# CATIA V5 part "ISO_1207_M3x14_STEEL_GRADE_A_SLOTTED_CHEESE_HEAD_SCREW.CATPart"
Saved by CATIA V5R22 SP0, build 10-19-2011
Part number: ISO 1207 SCREW M3x14 STEEL GRADE A SLOTTED CHEESE HEAD
Publications: "Mating Face", "Axis"
Bounding box of the stored display mesh (mm): x -16 to 0, y -2.741 to 2.741, z -2.75 to 2.75
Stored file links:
  D:\PER\CAO_PER_MODIF_2025\CAO_PER_pick&place_2024P\Sous_Ensemble_Flacon\ISO_1207_M3x14_STEEL_GRADE_A_SLOTTED_CHEESE_HEAD_SCREW.CATPart
  C:\Program Files\Dassault Systemes\B22\win_b64\startup\components\MechanicalStandardParts\EN_Standards\Design_Tables\EN_ISO_1207_GRADE_A_SLOTTED_CHEESE_HEAD_SCREW.txt
  C:\Program Files\Dassault Systemes\B22\win_b64\startup\components\MechanicalStandardParts\ISO_Standards\Design_Tables\ISO_1207_GRADE_A_SLOTTED_CHEESE_HEAD_SCREW.txt
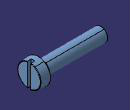
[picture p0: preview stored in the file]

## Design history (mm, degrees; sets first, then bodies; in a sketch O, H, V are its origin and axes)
Parameters
  d_dia = 3 mm
  dk_nom_head_dia = 5.5 mm
  k_max_head_depth = 2 mm
  n_nom_Slot_Width = 0.8 mm
  t_min_Slot_Depth = 0.85 mm
  r_min = 0.1 mm
  p_pitch = 0.5 mm
  Threading = 13 mm
  l_Length_nom = 14 mm
Body1 "PartBody" (main body)
  Sketch1 on zx-plane, origin (0, 0, 0), H (-1, 0, 0), V (0, 0, 1)
    line L1 (0, 0) -> (0, 2.575)
    line L2 (0, 2.575) -> (2, 2.75)
    point P2 (2, 2.75)
    line L3 (2, 2.75) -> (2, 1.4375)
    axis line L4 (-15.2845, 0) -> (155.0819, 0)
    reference intersected line E1 through (1000000, 0) direction (-1, 0) from xy-plane
    line L5 (2, 1.4375) -> (2.5, 1.4375)
    point P5 (3, 1.5)
    line L6 (3, 1.5) -> (16, 1.5)
    point P6 (16, 1.5)
    line L7 (16, 1.5) -> (16, 0)
    point P7 (16, 0)
    line L8 (3, 1.5) -> (2.5, 1.4375)
    point P9 (2.5, 1.4375)
    distance L1 P2 = 2 {= k_max_head_depth}
    distance P2 L4 = 2.75 {= dk_nom_head_dia /2}
    angle L4 L2 = 175
    length L7 = 1.5 {= d_dia /2}
    distance L5 L4 = 1.4375 {= (d_dia -(p_pitch/4))/2}
    distance P6 P5 = 13 {= Threading}
    distance L7 L1 = 16 {= l_Length_nom +k_max_head_depth}
    distance P9 P5 H = 0.5 {= p_pitch}
    vertical: L1 V, L3 V, L7 V
    horizontal: L4 H, L5 H
    coincidence: L4 E1, P7 L4
    parallelism: L6 L5
  Shaft1: profile Sketch1, axis Sketch1.L4, angle 360
  Fillet1: radius 0.1 {= r_min}, on edge [face of Shaft1 | face of Shaft1]
  Sketch2 on xy-plane, origin (0, 0, 0), H (1, 0, 0), V (0, 1, 0)
    line L1 (0, 0.4) -> (-0.85, 0.4)
    line L2 (-0.85, 0.4) -> (-0.85, -0.4)
    line L3 (-0.85, -0.4) -> (0, -0.4)
    line L4 (0, -0.4) -> (0, 0.4)
    distance O L2 = 0.85 {= t_min_Slot_Depth}
    distance H L1 = 0.4 {= n_nom_Slot_Width /2}
    distance H L3 = 0.4 {= n_nom_Slot_Width /2}
    vertical: L2 V
    coincidence: L4 V
  Pocket1: profile Sketch2, direction (0, 0, -1), through (limit type 3), opposite side length 20
  Fillet2: radius 0.1 {= r_min}, on edge [face of Shaft1 | face of Shaft1]
  Thread1: diameter 3 {= d_dia}, depth 13 {= Threading}, pitch 1, on face of Shaft1, from face of Shaft1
